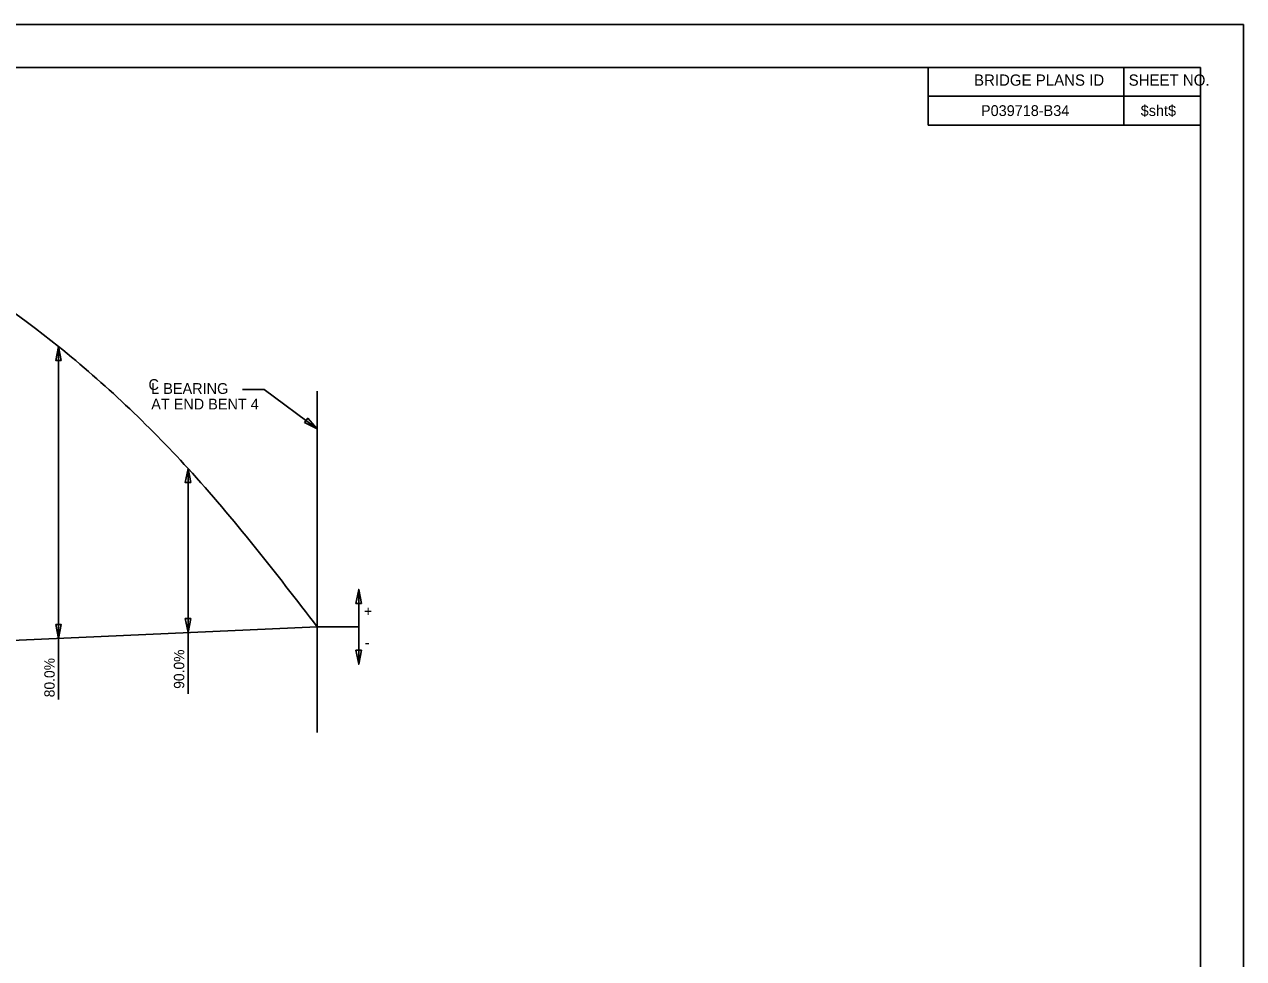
# Model space of a CAD drawing. Extents: x -125.5 to -89.4, y -5.1 to 16.9.
# Drawn here: x -103.65 to -89.53, y 6.12 to 16.93 of the extents above; entities that cross this region are included whole.
import ezdxf

# ---------------------------------------------------------------- set-up
doc = ezdxf.new("R2010")
doc.units = 0
for name, color, linetype in [('BR_AUTO DIMENSION', 7, 'Continuous'), ('BR_BORDER LINES', 7, 'Continuous'), ('BR_CENTER LINES', 7, 'Continuous'), ('BR_TABLE LINES', 7, 'Continuous'), ('BR_TEXT', 7, 'Continuous'), ('Level 31', 7, 'Continuous')]:
    doc.layers.add(name, color=color, linetype=linetype)

msp = doc.modelspace()

# ---------------------------------------------------------------- linework, layer by layer
at = {"layer": 'BR_AUTO DIMENSION'}
for p, q in [((-101.124, 12.709), (-100.87, 12.709)), ((-100.87, 12.709), (-100.257, 12.25)), ((-100.257, 9.96), (-99.777, 9.96))]:
    msp.add_line(p, q, dxfattribs=at)
for points in [[(-103.222, 13.043), (-103.253, 13.205), (-103.285, 13.043)], [(-100.405, 12.324), (-100.257, 12.25), (-100.367, 12.374)], [(-101.722, 11.63), (-101.753, 11.793), (-101.785, 11.63)], [(-99.746, 10.231), (-99.777, 10.393), (-99.809, 10.231)], [(-101.785, 10.055), (-101.753, 9.893), (-101.722, 10.055)], [(-103.285, 9.988), (-103.253, 9.825), (-103.222, 9.988)], [(-99.746, 9.689), (-99.777, 9.527), (-99.809, 9.689)]]:
    msp.add_lwpolyline(points, close=True, dxfattribs=at)
at = {"layer": 'BR_BORDER LINES'}
for p, q in [((-90.033, 16.434), (-123.699, 16.434)), ((-93.186, 15.767), (-93.186, 16.434)), ((-90.919, 15.767), (-90.919, 16.434)), ((-90.033, -4.566), (-90.033, 16.434)), ((-93.186, 16.104), (-90.033, 16.104)), ((-90.919, 16.104), (-90.033, 16.104)), ((-90.033, 15.767), (-93.186, 15.767))]:
    msp.add_line(p, q, dxfattribs=at)
at = {"layer": 'BR_CENTER LINES'}
msp.add_line((-100.257, 8.736), (-100.257, 12.689), dxfattribs=at)
at = {"layer": 'BR_TABLE LINES'}
for p, q in [((-103.253, 9.119), (-103.253, 13.205)), ((-101.753, 9.186), (-101.753, 11.793)), ((-99.777, 9.96), (-99.777, 10.393)), ((-100.257, 9.96), (-115.253, 9.285)), ((-99.777, 9.96), (-99.777, 9.527))]:
    msp.add_line(p, q, dxfattribs=at)
msp.add_lwpolyline([(-123.699, 16.434), (-90.033, 16.434), (-90.033, -4.566), (-123.699, -4.566)], close=True, dxfattribs=at)
msp.add_spline([(-115.253, 9.285), (-113.753, 11.123), (-112.253, 12.68), (-110.753, 13.858), (-109.253, 14.605), (-107.753, 14.913), (-106.253, 14.78), (-104.753, 14.208), (-103.253, 13.205), (-101.753, 11.793), (-100.257, 9.96)], degree=3, dxfattribs=at)
at = {"layer": 'Level 31'}
msp.add_line((-89.533, 16.934), (-125.533, 16.934), dxfattribs=at)
msp.add_lwpolyline([(-125.533, 16.934), (-125.533, -5.066), (-89.533, -5.066), (-89.533, 16.934)], dxfattribs=at)

# ---------------------------------------------------------------- texts
at = {"layer": 'BR_AUTO DIMENSION'}
for s, p in [('C', (-102.211, 12.702)), ('L BEARING', (-102.179, 12.656)), ('AT END BENT 4', (-102.179, 12.476))]:
    msp.add_text(s, height=0.125, dxfattribs=at).set_placement(p)
at = {"layer": 'BR_TEXT'}
for s, height, p in [('BRIDGE PLANS ID', 0.13, (-92.654, 16.224)), ('SHEET NO.', 0.13, (-90.864, 16.224)), ('P039718-B34', 0.125, (-92.573, 15.873)), ('$sht$', 0.125, (-90.724, 15.873)), ('-', 0.12, (-99.706, 9.719))]:
    msp.add_text(s, height=height, dxfattribs=at).set_placement(p)
for s, rotation, p in [('+', 360, (-99.716, 10.081)), ('90.0%', 90, (-101.797, 9.242)), ('80.0%', 90, (-103.297, 9.144))]:
    msp.add_text(s, height=0.12, rotation=rotation, dxfattribs=at).set_placement(p)

doc.saveas('drawing.dxf')
